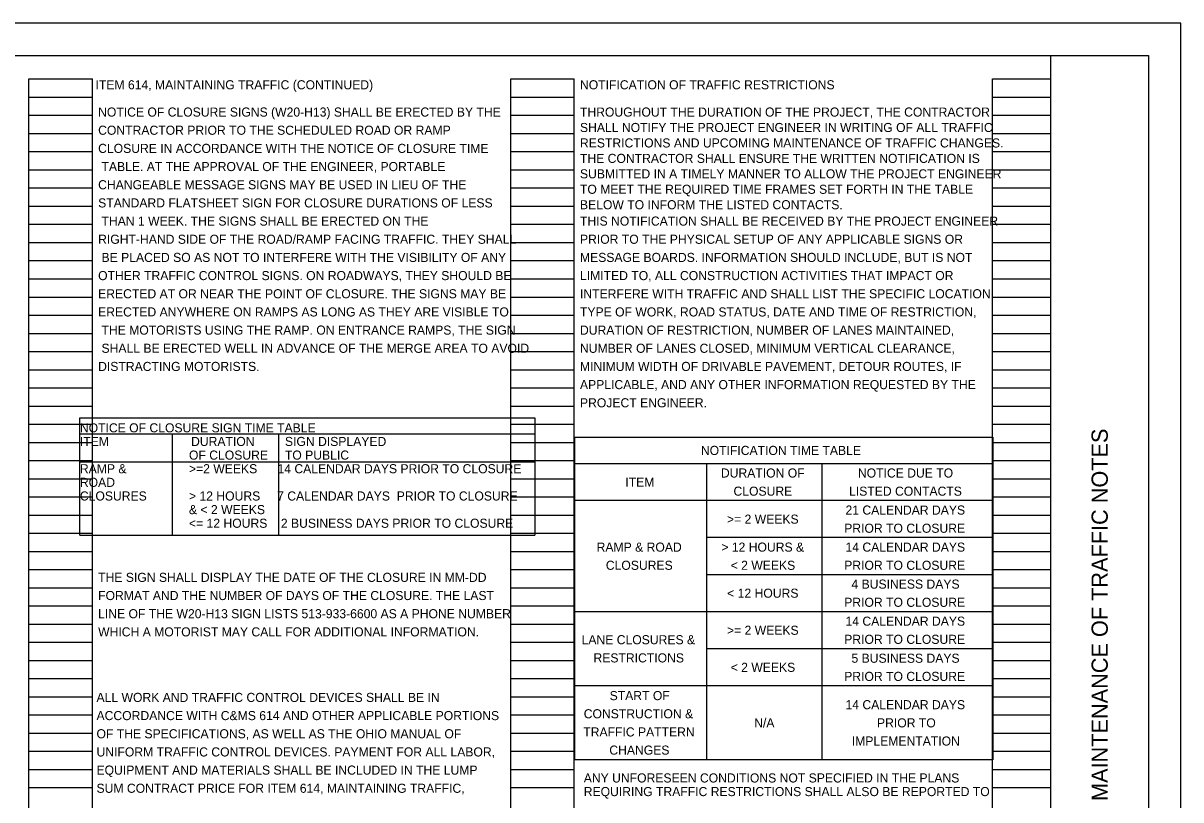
# Model space of a CAD drawing. Extents: x -21.1 to 72.2, y 0 to 46.6.
# Drawn here: x 16.17 to 34, y 10.03 to 22 of the extents above; entities that cross this region are included whole.
import ezdxf

# ---------------------------------------------------------------- set-up
doc = ezdxf.new("R2010")
doc.units = 0
for name, color, linetype in [('SH_Border', 7, 'Continuous'), ('SH_Cut_Line', 7, 'Continuous'), ('SH_Data', 7, 'Continuous'), ('SH_Text', 7, 'Continuous')]:
    doc.layers.add(name, color=color, linetype=linetype)

msp = doc.modelspace()

# ---------------------------------------------------------------- linework, layer by layer
at = {"layer": 'SH_Border'}
msp.add_line((32, 0.5), (32, 21.5), dxfattribs=at)
msp.add_lwpolyline([(1.5, 21.5), (33.5, 21.5), (33.5, 0.5), (1.5, 0.5)], close=True, dxfattribs=at)
at = {"layer": 'SH_Cut_Line'}
msp.add_lwpolyline([(0, 0), (34, 0), (34, 22), (0, 22)], close=True, dxfattribs=at)
at = {"layer": 'SH_Data'}
for p, q in [((16.26, 0.98), (16.26, 21.14)), ((16.26, 21.14), (17.24, 21.14)), ((17.24, 0.98), (17.24, 21.14)), ((23.68, 0.98), (23.68, 21.14)), ((23.68, 21.14), (24.66, 21.14)), ((24.66, 0.98), (24.66, 21.14)), ((31.1, 0.98), (31.1, 21.14)), ((31.1, 21.14), (32, 21.14)), ((32, 0.98), (32, 21.14)), ((16.26, 20.86), (17.24, 20.86)), ((23.68, 20.86), (24.66, 20.86)), ((31.1, 20.86), (32, 20.86)), ((16.26, 20.58), (17.24, 20.58)), ((23.68, 20.58), (24.66, 20.58)), ((31.1, 20.58), (32, 20.58)), ((16.26, 20.3), (17.24, 20.3)), ((23.68, 20.3), (24.66, 20.3)), ((31.1, 20.3), (32, 20.3)), ((16.26, 20.02), (17.24, 20.02)), ((23.68, 20.02), (24.66, 20.02)), ((31.1, 20.02), (32, 20.02)), ((16.26, 19.74), (17.24, 19.74)), ((23.68, 19.74), (24.66, 19.74)), ((31.1, 19.74), (32, 19.74)), ((16.26, 19.46), (17.24, 19.46)), ((23.68, 19.46), (24.66, 19.46)), ((31.1, 19.46), (32, 19.46)), ((16.26, 19.18), (17.24, 19.18)), ((23.68, 19.18), (24.66, 19.18)), ((31.1, 19.18), (32, 19.18)), ((16.26, 18.9), (17.24, 18.9)), ((23.68, 18.9), (24.66, 18.9)), ((31.1, 18.9), (32, 18.9)), ((16.26, 18.62), (17.24, 18.62)), ((23.68, 18.62), (24.66, 18.62)), ((31.1, 18.62), (32, 18.62)), ((16.26, 18.34), (17.24, 18.34)), ((23.68, 18.34), (24.66, 18.34)), ((31.1, 18.34), (32, 18.34)), ((16.26, 18.06), (17.24, 18.06)), ((23.68, 18.06), (24.66, 18.06)), ((31.1, 18.06), (32, 18.06)), ((16.26, 17.78), (17.24, 17.78)), ((23.68, 17.78), (24.66, 17.78)), ((31.1, 17.78), (32, 17.78)), ((16.26, 17.5), (17.24, 17.5)), ((23.68, 17.5), (24.66, 17.5)), ((31.1, 17.5), (32, 17.5)), ((16.26, 17.22), (17.24, 17.22)), ((23.68, 17.22), (24.66, 17.22)), ((31.1, 17.22), (32, 17.22)), ((16.26, 16.94), (17.24, 16.94)), ((23.68, 16.94), (24.66, 16.94)), ((31.1, 16.94), (32, 16.94)), ((16.26, 16.66), (17.24, 16.66)), ((23.68, 16.66), (24.66, 16.66)), ((31.1, 16.66), (32, 16.66)), ((16.26, 16.38), (17.24, 16.38)), ((23.68, 16.38), (24.66, 16.38)), ((31.1, 16.38), (32, 16.38)), ((16.26, 16.1), (17.24, 16.1)), ((23.68, 16.1), (24.66, 16.1)), ((31.1, 16.1), (32, 16.1)), ((16.26, 15.82), (17.24, 15.82)), ((23.68, 15.82), (24.66, 15.82)), ((31.1, 15.82), (32, 15.82)), ((16.26, 15.54), (17.24, 15.54)), ((23.68, 15.54), (24.66, 15.54)), ((31.1, 15.54), (32, 15.54)), ((16.26, 15.26), (17.24, 15.26)), ((23.68, 15.26), (24.66, 15.26)), ((31.1, 15.26), (32, 15.26)), ((16.26, 14.98), (17.24, 14.98)), ((23.68, 14.98), (24.66, 14.98)), ((31.1, 14.98), (32, 14.98)), ((16.26, 14.7), (17.24, 14.7)), ((23.68, 14.7), (24.66, 14.7)), ((31.1, 14.7), (32, 14.7)), ((16.26, 14.42), (17.24, 14.42)), ((23.68, 14.42), (24.66, 14.42)), ((31.1, 14.42), (32, 14.42)), ((16.26, 14.14), (17.24, 14.14)), ((23.68, 14.14), (24.66, 14.14)), ((31.1, 14.14), (32, 14.14)), ((16.26, 13.86), (17.24, 13.86)), ((23.68, 13.86), (24.66, 13.86)), ((31.1, 13.86), (32, 13.86)), ((16.26, 13.58), (17.24, 13.58)), ((23.68, 13.58), (24.66, 13.58)), ((31.1, 13.58), (32, 13.58)), ((16.26, 13.3), (17.24, 13.3)), ((23.68, 13.3), (24.66, 13.3)), ((31.1, 13.3), (32, 13.3)), ((16.26, 13.02), (17.24, 13.02)), ((23.68, 13.02), (24.66, 13.02)), ((31.1, 13.02), (32, 13.02)), ((16.26, 12.74), (17.24, 12.74)), ((23.68, 12.74), (24.66, 12.74)), ((31.1, 12.74), (32, 12.74)), ((16.26, 12.46), (17.24, 12.46)), ((23.68, 12.46), (24.66, 12.46)), ((31.1, 12.46), (32, 12.46)), ((16.26, 12.18), (17.24, 12.18)), ((23.68, 12.18), (24.66, 12.18)), ((31.1, 12.18), (32, 12.18)), ((16.26, 11.9), (17.24, 11.9)), ((23.68, 11.9), (24.66, 11.9)), ((31.1, 11.9), (32, 11.9)), ((16.26, 11.62), (17.24, 11.62)), ((23.68, 11.62), (24.66, 11.62)), ((31.1, 11.62), (32, 11.62)), ((16.26, 11.34), (17.24, 11.34)), ((23.68, 11.34), (24.66, 11.34)), ((31.1, 11.34), (32, 11.34)), ((16.26, 11.06), (17.24, 11.06)), ((23.68, 11.06), (24.66, 11.06)), ((31.1, 11.06), (32, 11.06)), ((16.26, 10.78), (17.24, 10.78)), ((23.68, 10.78), (24.66, 10.78)), ((31.1, 10.78), (32, 10.78)), ((16.26, 10.5), (17.24, 10.5)), ((23.68, 10.5), (24.66, 10.5)), ((31.1, 10.5), (32, 10.5)), ((16.26, 10.22), (17.24, 10.22)), ((23.68, 10.22), (24.66, 10.22)), ((31.1, 10.22), (32, 10.22))]:
    msp.add_line(p, q, dxfattribs=at)
at = {"layer": 'SH_Text'}
for p, q in [((24.051, 15.917), (24.051, 14.111)), ((17.046, 14.111), (17.046, 15.666)), ((18.467, 15.666), (18.467, 14.111)), ((20.104, 15.666), (20.104, 14.111)), ((17.046, 15.239), (24.051, 15.239)), ((24.667, 15.213), (31.107, 15.213)), ((26.7, 10.647), (26.7, 15.213)), ((28.476, 10.647), (28.476, 15.213)), ((31.107, 14.642), (24.667, 14.642)), ((17.046, 14.111), (24.051, 14.111)), ((31.107, 14.072), (26.7, 14.072)), ((31.107, 13.501), (26.7, 13.501)), ((31.107, 12.93), (24.667, 12.93)), ((31.107, 12.359), (26.7, 12.359)), ((31.107, 11.789), (24.667, 11.789))]:
    msp.add_line(p, q, dxfattribs=at)
for points in [[(24.051, 15.666), (17.046, 15.666), (17.046, 15.918), (24.051, 15.918)], [(24.667, 15.619), (31.107, 15.619), (31.107, 10.647), (24.667, 10.647)]]:
    msp.add_lwpolyline(points, close=True, dxfattribs=at)

# ---------------------------------------------------------------- texts
at = {"layer": 'SH_Data'}
msp.add_text('MAINTENANCE OF TRAFFIC NOTES', height=0.25, rotation=90, dxfattribs=at).set_placement((32.875, 10.014))
at = {"layer": 'SH_Text'}
for s, p in [('ITEM 614, MAINTAINING TRAFFIC (CONTINUED)', (17.287, 20.98)), ('NOTIFICATION OF TRAFFIC RESTRICTIONS', (24.747, 20.98)), ('NOTICE OF CLOSURE SIGNS (W20-H13) SHALL BE ERECTED BY THE ', (17.327, 20.56)), ('THROUGHOUT THE DURATION OF THE PROJECT, THE CONTRACTOR', (24.747, 20.56)), ('CONTRACTOR PRIOR TO THE SCHEDULED ROAD OR RAMP ', (17.327, 20.28)), ('SHALL NOTIFY THE PROJECT ENGINEER IN WRITING OF ALL TRAFFIC', (24.747, 20.322)), ('RESTRICTIONS AND UPCOMING MAINTENANCE OF TRAFFIC CHANGES.', (24.747, 20.084)), ('CLOSURE IN ACCORDANCE WITH THE NOTICE OF CLOSURE TIME', (17.327, 20)), ('THE CONTRACTOR SHALL ENSURE THE WRITTEN NOTIFICATION IS', (24.747, 19.846)), (' TABLE. AT THE APPROVAL OF THE ENGINEER, PORTABLE ', (17.327, 19.72)), ('SUBMITTED IN A TIMELY MANNER TO ALLOW THE PROJECT ENGINEER', (24.747, 19.608)), ('CHANGEABLE MESSAGE SIGNS MAY BE USED IN LIEU OF THE ', (17.327, 19.44)), ('TO MEET THE REQUIRED TIME FRAMES SET FORTH IN THE TABLE', (24.747, 19.37)), ('STANDARD FLATSHEET SIGN FOR CLOSURE DURATIONS OF LESS', (17.327, 19.16)), ('BELOW TO INFORM THE LISTED CONTACTS.', (24.747, 19.132)), (' THAN 1 WEEK. THE SIGNS SHALL BE ERECTED ON THE ', (17.327, 18.88)), ('THIS NOTIFICATION SHALL BE RECEIVED BY THE PROJECT ENGINEER ', (24.747, 18.88)), ('RIGHT-HAND SIDE OF THE ROAD/RAMP FACING TRAFFIC. THEY SHALL', (17.327, 18.6)), ('PRIOR TO THE PHYSICAL SETUP OF ANY APPLICABLE SIGNS OR ', (24.747, 18.6)), (' BE PLACED SO AS NOT TO INTERFERE WITH THE VISIBILITY OF ANY ', (17.327, 18.32)), ('MESSAGE BOARDS. INFORMATION SHOULD INCLUDE, BUT IS NOT ', (24.747, 18.32)), ('OTHER TRAFFIC CONTROL SIGNS. ON ROADWAYS, THEY SHOULD BE ', (17.327, 18.04)), ('LIMITED TO, ALL CONSTRUCTION ACTIVITIES THAT IMPACT OR ', (24.747, 18.04)), ('ERECTED AT OR NEAR THE POINT OF CLOSURE. THE SIGNS MAY BE ', (17.327, 17.76)), ('INTERFERE WITH TRAFFIC AND SHALL LIST THE SPECIFIC LOCATION, ', (24.747, 17.76)), ('ERECTED ANYWHERE ON RAMPS AS LONG AS THEY ARE VISIBLE TO', (17.327, 17.48)), ('TYPE OF WORK, ROAD STATUS, DATE AND TIME OF RESTRICTION, ', (24.747, 17.48)), (' THE MOTORISTS USING THE RAMP. ON ENTRANCE RAMPS, THE SIGN', (17.327, 17.2)), ('DURATION OF RESTRICTION, NUMBER OF LANES MAINTAINED, ', (24.747, 17.2)), (' SHALL BE ERECTED WELL IN ADVANCE OF THE MERGE AREA TO AVOID ', (17.327, 16.92)), ('NUMBER OF LANES CLOSED, MINIMUM VERTICAL CLEARANCE, ', (24.747, 16.92)), ('DISTRACTING MOTORISTS.', (17.327, 16.64)), ('MINIMUM WIDTH OF DRIVABLE PAVEMENT, DETOUR ROUTES, IF ', (24.747, 16.64)), ('APPLICABLE, AND ANY OTHER INFORMATION REQUESTED BY THE ', (24.747, 16.36)), ('PROJECT ENGINEER.', (24.747, 16.08)), ('NOTICE OF CLOSURE SIGN TIME TABLE', (17.046, 15.694)), ('ITEM       ', (17.046, 15.484)), ('      DURATION         SIGN DISPLAYED', (18.446, 15.484)), ('OF CLOSURE     TO PUBLIC', (18.726, 15.274)), ('NOTIFICATION TIME TABLE', (26.609, 15.346)), ('RAMP &     ', (17.046, 15.064)), ('>=2 WEEKS      14 CALENDAR DAYS PRIOR TO CLOSURE', (18.726, 15.064)), ('ROAD', (17.046, 14.854)), ('ITEM', (25.446, 14.858)), ('DURATION OF', (26.917, 14.998)), ('NOTICE DUE TO', (29.027, 14.998)), ('CLOSURE', (27.111, 14.718)), ('LISTED CONTACTS', (28.891, 14.718)), ('CLOSURES  ', (17.046, 14.644)), ('> 12 HOURS     7 CALENDAR DAYS  PRIOR TO CLOSURE', (18.726, 14.644)), ('& < 2 WEEKS    ', (18.726, 14.434)), ('21 CALENDAR DAYS', (28.836, 14.427)), ('<= 12 HOURS    2 BUSINESS DAYS PRIOR TO CLOSURE', (18.726, 14.224)), ('>= 2 WEEKS', (27.011, 14.287)), ('PRIOR TO CLOSURE', (28.816, 14.147)), ('RAMP & ROAD', (25.003, 13.856)), ('> 12 HOURS &', (26.924, 13.856)), ('14 CALENDAR DAYS', (28.836, 13.856)), ('CLOSURES', (25.145, 13.576)), ('< 2 WEEKS', (27.068, 13.576)), ('PRIOR TO CLOSURE', (28.816, 13.576)), ('THE SIGN SHALL DISPLAY THE DATE OF THE CLOSURE IN MM-DD ', (17.327, 13.39)), ('4 BUSINESS DAYS', (28.928, 13.286)), ('FORMAT AND THE NUMBER OF DAYS OF THE CLOSURE. THE LAST ', (17.327, 13.11)), ('< 12 HOURS', (27.014, 13.146)), ('PRIOR TO CLOSURE', (28.816, 13.006)), ('LINE OF THE W20-H13 SIGN LISTS 513-933-6600 AS A PHONE NUMBER ', (17.327, 12.83)), ('14 CALENDAR DAYS', (28.836, 12.715)), ('WHICH A MOTORIST MAY CALL FOR ADDITIONAL INFORMATION.', (17.327, 12.55)), ('>= 2 WEEKS', (27.011, 12.575)), ('LANE CLOSURES &', (24.772, 12.429)), ('PRIOR TO CLOSURE', (28.816, 12.435)), ('RESTRICTIONS', (24.955, 12.149)), ('< 2 WEEKS', (27.068, 12.004)), ('5 BUSINESS DAYS', (28.928, 12.144)), ('PRIOR TO CLOSURE', (28.816, 11.864)), ('ALL WORK AND TRAFFIC CONTROL DEVICES SHALL BE IN ', (17.302, 11.54)), ('START OF', (25.204, 11.568)), ('CONSTRUCTION &', (24.805, 11.288)), ('14 CALENDAR DAYS', (28.836, 11.428)), ('ACCORDANCE WITH C&MS 614 AND OTHER APPLICABLE PORTIONS ', (17.302, 11.26)), ('N/A', (27.43, 11.148)), ('PRIOR TO', (29.321, 11.148)), ('OF THE SPECIFICATIONS, AS WELL AS THE OHIO MANUAL OF ', (17.302, 10.98)), ('TRAFFIC PATTERN', (24.798, 11.008)), ('IMPLEMENTATION', (28.933, 10.868)), ('UNIFORM TRAFFIC CONTROL DEVICES. PAYMENT FOR ALL LABOR, ', (17.302, 10.7)), ('CHANGES', (25.199, 10.728)), ('EQUIPMENT AND MATERIALS SHALL BE INCLUDED IN THE LUMP ', (17.302, 10.42)), ('ANY UNFORESEEN CONDITIONS NOT SPECIFIED IN THE PLANS', (24.805, 10.299)), ('SUM CONTRACT PRICE FOR ITEM 614, MAINTAINING TRAFFIC, ', (17.302, 10.14)), ('REQUIRING TRAFFIC RESTRICTIONS SHALL ALSO BE REPORTED TO', (24.805, 10.089))]:
    msp.add_text(s, height=0.14, dxfattribs=at).set_placement(p)

doc.saveas('drawing.dxf')
